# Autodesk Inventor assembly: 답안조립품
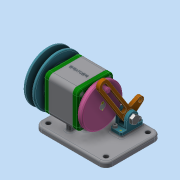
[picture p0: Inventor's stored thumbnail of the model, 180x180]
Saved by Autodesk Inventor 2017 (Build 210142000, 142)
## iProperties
Part Number: 답안조립품
Material: 일반
Document SubType Name: Assembly
Designer: 222
Author: 222
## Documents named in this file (19)
- C:\Users\222\Desktop\601106V1060\답안조립품.iam
- C:\Users\222\Desktop\601106V1060\본체.ipt
- C:\Users\222\Desktop\601106V1060\V-벨트풀리.ipt
- C:\Users\222\Desktop\601106V1060\너트 M8.ipt
- C:\Users\222\Desktop\601106V1060\너트 M10x1.ipt
- C:\Users\222\Desktop\601106V1060\돌림판.ipt
- C:\Users\222\Desktop\601106V1060\멈춤나사 M3x5.ipt
- C:\Users\222\Desktop\601106V1060\베어링 6004.ipt
- C:\Users\222\Desktop\601106V1060\볼트 M4.ipt
- C:\Users\222\Desktop\601106V1060\오일 실 17 30 5.ipt
- C:\Users\222\Desktop\601106V1060\와셔 8x15.5.ipt
- C:\Users\222\Desktop\601106V1060\축.ipt
- C:\Users\222\Desktop\601106V1060\커버.ipt
- C:\Users\222\Desktop\601106V1060\크랭크.ipt
- C:\Users\222\Desktop\601106V1060\키 4 x 4 x 8.ipt
- C:\Users\222\Desktop\601106V1060\키 5 x 5 x 12.ipt
- C:\Users\222\Desktop\601106V1060\핀 3 x 8.ipt
- C:\Users\222\Desktop\601106V1060\힌지 축.ipt
- C:\Users\222\Desktop\601106V1060\힌지.ipt
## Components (3 placed, 2 different names)
1. V-벨트풀리:1
2. 핀 3 x 8:1 — 플러쉬:1
3. 핀 3 x 8:2 — 플러쉬:2
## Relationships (2: Flush 2)
- 플러쉬:1 [Flush]: 핀 3 x 8:1
- 플러쉬:2 [Flush]: 핀 3 x 8:2
